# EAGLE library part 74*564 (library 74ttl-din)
Inverting 8-bit D type FLIP FLOP
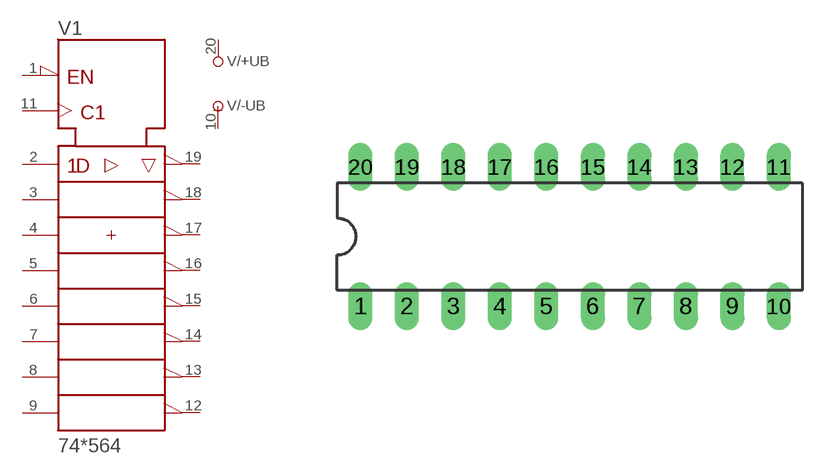
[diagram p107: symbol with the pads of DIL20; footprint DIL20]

Designator prefix V; gates /+UB=+UB /-UB=-UB 1=564

## 74564N  [DIL20]
1  1:OC\  in
2  1:1D  in
3  1:2D  in
4  1:3D  in
5  1:4D  in
6  1:5D  in
7  1:6D  in
8  1:7D  in
9  1:8D  in
10  /-UB:-UB  pwr
11  1:CLK  in
12  1:8Q\  hiz
13  1:7Q\  hiz
14  1:6Q\  hiz
15  1:5Q\  hiz
16  1:4Q\  hiz
17  1:3Q\  hiz
18  1:2Q\  hiz
19  1:1Q\  hiz
20  /+UB:+UB  pwr

## Footprint DIL20 (pad centres in mm)
Dual In Line Package
drill 0.813 long: 1 -11.43,-3.81; 2 -8.89,-3.81; 3 -6.35,-3.81; 4 -3.81,-3.81; 5 -1.27,-3.81; 6 1.27,-3.81; 7 3.81,-3.81; 8 6.35,-3.81; 9 8.89,-3.81; 10 11.43,-3.81; 11 11.43,3.81; 12 8.89,3.81; 13 6.35,3.81; 14 3.81,3.81; 15 1.27,3.81; 16 -1.27,3.81; 17 -3.81,3.81; 18 -6.35,3.81; 19 -8.89,3.81; 20 -11.43,3.81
